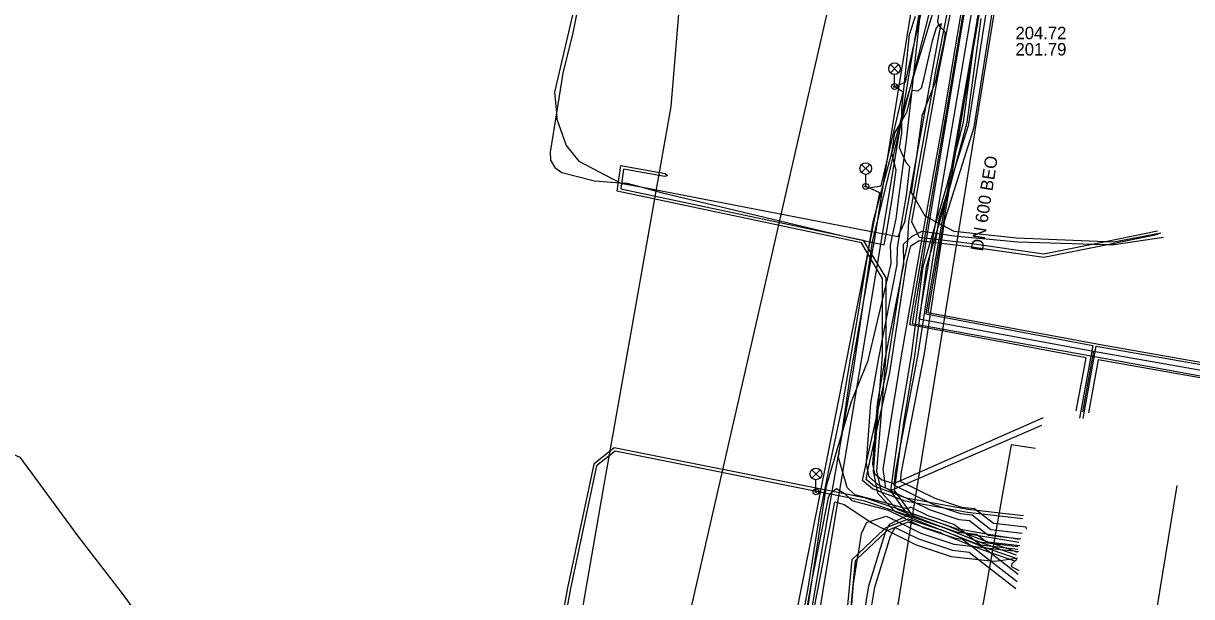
# Model space of a CAD drawing. Extents: x -596228 to -595156, y -1161235 to -1159373.
# Drawn here: x -595916.2 to -595841.1, y -1160088.8 to -1160051.9 of the extents above; entities that cross this region are included whole.
import ezdxf

# ---------------------------------------------------------------- set-up
doc = ezdxf.new("R2010")
doc.units = 0
for name, color, linetype in [('Vrstva 1', 7, 'Continuous'), ('Vrstva 12', 7, 'Continuous'), ('Vrstva 14', 7, 'Continuous'), ('Vrstva 25', 7, 'Continuous'), ('Vrstva 26', 7, 'Continuous'), ('Vrstva 33', 7, 'Continuous'), ('Vrstva 37', 7, 'Continuous'), ('Vrstva 4', 7, 'Continuous'), ('Vrstva 42', 7, 'Continuous'), ('Vrstva 44', 7, 'Continuous'), ('Vrstva 53', 7, 'Continuous'), ('Vrstva 55', 7, 'Continuous')]:
    doc.layers.add(name, color=color, linetype=linetype)

msp = doc.modelspace()

# ---------------------------------------------------------------- linework, layer by layer
at = {"layer": 'Vrstva 1'}
for p, q in [((-595878.63, -1160112.85), (-595863.23, -1160045.57)), ((-595853.63, -1160050.15), (-595860.88, -1160094.77))]:
    msp.add_line(p, q, dxfattribs=at)
at = {"layer": 'Vrstva 12'}
msp.add_lwpolyline([(-595873.83, -1160048.21), (-595874.58, -1160057.28), (-595878.97, -1160081.97), (-595886.34, -1160124.44), (-595887.99, -1160133.91), (-595889.12, -1160140.39), (-595891.94, -1160156.53), (-595892.78, -1160161.36), (-595893.73, -1160166.74)], dxfattribs=at)
at = {"layer": 'Vrstva 14'}
msp.add_lwpolyline([(-595903.525, -1160327.591), (-595903.438, -1160327.11), (-595895.992, -1160276.218), (-595895.362, -1160271.913), (-595894.416, -1160266.829), (-595893.077, -1160257.958), (-595892.847, -1160256.335), (-595887.94, -1160223.167), (-595881.65, -1160186.81), (-595876.814, -1160159.541), (-595869.649, -1160117.522), (-595863.209, -1160078.856), (-595858.091, -1160048.124), (-595857.576, -1160045.207), (-595855.994, -1160045.422), (-595855.543, -1160042.523), (-595857.05, -1160042.292), (-595850.5, -1160006.311), (-595840.026, -1160007.969)], dxfattribs=at)
at = {"layer": 'Vrstva 25'}
for points in [[(-595848.913, -1160014.604), (-595851.258, -1160027.646), (-595852.717, -1160036.135), (-595854.448, -1160046.34), (-595856.426, -1160058.005), (-595858.649, -1160070.917), (-595847.414, -1160073.01)], [(-595847.414, -1160073.01), (-595847.739, -1160074.765), (-595848.135, -1160076.908)], [(-595847.414, -1160073.01), (-595832.961, -1160075.546), (-595834.372, -1160084.741), (-595836.409, -1160097.343), (-595826.834, -1160101.575), (-595815.738, -1160106.435), (-595812.472, -1160107.597), (-595809.986, -1160108.26), (-595808.287, -1160108.633), (-595806.429, -1160108.923), (-595791.586, -1160111.411), (-595780.465, -1160113.2), (-595779.852, -1160109.66)]]:
    msp.add_lwpolyline(points, dxfattribs=at)
at = {"layer": 'Vrstva 26'}
for points in [[(-595848.334, -1160014.211), (-595850.766, -1160027.733), (-595852.224, -1160036.219), (-595853.955, -1160046.424), (-595855.933, -1160058.089), (-595858.073, -1160070.515), (-595847.323, -1160072.519)], [(-595847.898, -1160073.429), (-595859.226, -1160071.318), (-595856.918, -1160057.921), (-595854.941, -1160046.256), (-595853.21, -1160036.051), (-595851.751, -1160027.56), (-595849.492, -1160014.998)], [(-595847.328, -1160072.518), (-595832.393, -1160075.138), (-595833.878, -1160084.819), (-595835.854, -1160097.042), (-595826.633, -1160101.117), (-595815.554, -1160105.97), (-595812.323, -1160107.119), (-595809.868, -1160107.774), (-595808.195, -1160108.142), (-595806.349, -1160108.429), (-595791.505, -1160110.918), (-595780.873, -1160112.627), (-595780.345, -1160109.575)], [(-595848.528, -1160076.835), (-595848.132, -1160074.692), (-595847.898, -1160073.429)], [(-595847.111, -1160073.571), (-595847.345, -1160074.838), (-595847.741, -1160076.981)], [(-595779.429, -1160110.146), (-595780.056, -1160113.772), (-595791.667, -1160111.904), (-595806.509, -1160109.416), (-595808.38, -1160109.125), (-595810.104, -1160108.746), (-595812.62, -1160108.075), (-595815.923, -1160106.9), (-595827.035, -1160102.032), (-595836.965, -1160097.644), (-595834.866, -1160084.663), (-595833.53, -1160075.954), (-595847.111, -1160073.571)]]:
    msp.add_lwpolyline(points, dxfattribs=at)
at = {"layer": 'Vrstva 33'}
for p, q in [((-595860.475, -1160054.575), (-595859.945, -1160055.105)), ((-595860.475, -1160055.105), (-595859.945, -1160054.575)), ((-595860.21, -1160055.99), (-595860.21, -1160055.215)), ((-595862.325, -1160060.995), (-595861.795, -1160061.525)), ((-595862.325, -1160061.525), (-595861.795, -1160060.995)), ((-595862.06, -1160062.41), (-595862.06, -1160061.635)), ((-595865.525, -1160080.635), (-595864.995, -1160081.165)), ((-595865.525, -1160081.165), (-595864.995, -1160080.635)), ((-595865.26, -1160082.05), (-595865.26, -1160081.275))]:
    msp.add_line(p, q, dxfattribs=at)
for centre, radius in [((-595860.21, -1160054.84), 0.375), ((-595860.21, -1160055.99), 0.19), ((-595860.21, -1160055.99), 0.05), ((-595862.06, -1160061.26), 0.375), ((-595862.06, -1160062.41), 0.19), ((-595862.06, -1160062.41), 0.05), ((-595865.26, -1160080.9), 0.375), ((-595865.26, -1160082.05), 0.19), ((-595865.26, -1160082.05), 0.05)]:
    msp.add_circle(centre, radius, dxfattribs=at)
at = {"layer": 'Vrstva 37'}
for points in [[(-595851.153, -1160079.274), (-595852.714, -1160079.02), (-595862.455, -1160134.068), (-595836.577, -1160138.534)], [(-595842.059, -1160081.643), (-595848.753, -1160122.538), (-595834.439, -1160125.011), (-595836.577, -1160138.534)]]:
    msp.add_lwpolyline(points, dxfattribs=at)
at = {"layer": 'Vrstva 42'}
for points in [[(-595873.688, -1159960.969), (-595873.136, -1159957.91), (-595871.902, -1159958.088), (-595863.25, -1159959.53), (-595863.9, -1159965.29), (-595865.673, -1159976.949), (-595867.053, -1159989.854), (-595868.25, -1159989.709), (-595873.971, -1159989.019), (-595874.999, -1159988.861), (-595876.151, -1159992.513), (-595876.588, -1159993.79), (-595863.441, -1159998.192), (-595865.906, -1160011.02), (-595857.067, -1160012.572), (-595848.508, -1160014.294), (-595852.168, -1160035.065), (-595855.053, -1160052.565), (-595858.203, -1160070.6), (-595847.46, -1160072.642), (-595848.325, -1160077.311)], [(-595916.617, -1159981.581), (-595914.21, -1159982.379), (-595897.57, -1159987.853), (-595877.263, -1159994.535), (-595864.428, -1159998.802), (-595866.813, -1160011.736), (-595857.199, -1160013.352), (-595849.351, -1160014.93), (-595853.123, -1160036.433), (-595855.896, -1160052.235), (-595859.081, -1160071.227), (-595847.219, -1160073.379), (-595833.399, -1160075.892)], [(-595852.082, -1160085.098), (-595852.831, -1160085.013), (-595854.172, -1160084.86), (-595854.297, -1160084.763), (-595855.384, -1160083.917), (-595856.047, -1160083.842), (-595857.906, -1160083.223), (-595860.075, -1160082.16), (-595860.444, -1160081.979), (-595860.763, -1160081.822), (-595860.932, -1160080.592), (-595859.753, -1160073.316), (-595858.179, -1160064.287), (-595857.105, -1160058.32), (-595855.189, -1160046.9), (-595853.954, -1160042.986), (-595852.648, -1160041.748), (-595851.862, -1160041.003)], [(-595853.723, -1160047.284), (-595855.486, -1160058.519), (-595856.334, -1160061.214), (-595857.365, -1160064.492), (-595857.474, -1160065.204), (-595858.703, -1160073.211), (-595859.847, -1160079.116), (-595860.155, -1160080.704), (-595860.253, -1160081.627), (-595860.197, -1160081.654), (-595857.754, -1160082.852), (-595855.96, -1160083.449), (-595855.225, -1160083.533), (-595854.015, -1160084.476), (-595852.006, -1160084.704)], [(-595851.721, -1160084.459), (-595851.738, -1160084.333), (-595853.858, -1160084.091), (-595855.072, -1160083.147), (-595855.874, -1160083.057), (-595857.602, -1160082.481), (-595859.836, -1160081.386), (-595859.761, -1160080.774), (-595858.309, -1160073.279), (-595856.975, -1160064.582), (-595855.096, -1160058.611), (-595853.319, -1160047.289)], [(-595852.254, -1160087.365), (-595853.422, -1160086.457), (-595854.083, -1160085.943), (-595854.487, -1160085.629), (-595854.581, -1160085.556), (-595854.676, -1160085.482), (-595855.101, -1160085.152), (-595855.155, -1160085.11), (-595855.633, -1160084.738), (-595855.694, -1160084.69), (-595855.699, -1160084.687), (-595855.968, -1160084.478), (-595856.391, -1160084.149), (-595858.058, -1160083.594), (-595859.181, -1160083.043), (-595859.377, -1160083.136), (-595859.395, -1160083.144), (-595859.669, -1160083.071), (-595860.301, -1160082.903), (-595860.669, -1160082.805), (-595862.762, -1160082.247), (-595863.265, -1160081.765), (-595863.809, -1160079.844), (-595863.084, -1160074.815), (-595861.716, -1160067.103), (-595861.662, -1160066.801), (-595861.526, -1160066.033), (-595860.238, -1160057.936), (-595858.755, -1160048.787)], [(-595852.372, -1160086.12), (-595853.427, -1160085.75), (-595853.934, -1160085.572), (-595854.944, -1160085.217), (-595855.101, -1160085.152), (-595856.317, -1160084.65), (-595856.895, -1160084.411), (-595856.997, -1160084.369), (-595857.125, -1160084.316), (-595857.352, -1160084.24), (-595858.289, -1160083.926), (-595859.301, -1160083.587), (-595859.325, -1160083.554), (-595859.418, -1160083.422), (-595859.487, -1160083.326), (-595859.669, -1160083.071), (-595860.445, -1160081.986), (-595860.444, -1160081.979), (-595859.819, -1160077.445), (-595859.129, -1160073.285), (-595858.378, -1160067.559), (-595856.826, -1160062.303), (-595855.768, -1160058.271), (-595854.869, -1160051.583)], [(-595854.671, -1160051.617), (-595855.572, -1160058.309), (-595856.334, -1160061.214), (-595856.634, -1160062.357), (-595857.474, -1160065.204), (-595858.182, -1160067.601), (-595858.931, -1160073.315), (-595859.621, -1160077.475), (-595859.847, -1160079.116), (-595860.197, -1160081.654), (-595860.236, -1160081.934), (-595860.075, -1160082.16), (-595859.377, -1160083.136), (-595859.176, -1160083.418), (-595857.055, -1160084.129), (-595856.826, -1160084.223), (-595855.705, -1160084.686), (-595855.694, -1160084.69), (-595855.541, -1160084.754), (-595854.873, -1160085.03), (-595854.386, -1160085.201), (-595854.227, -1160085.257), (-595853.889, -1160085.375), (-595853.016, -1160085.682), (-595852.536, -1160085.851), (-595852.337, -1160085.921)], [(-595852.293, -1160085.769), (-595853.016, -1160085.682), (-595853.934, -1160085.572), (-595854.676, -1160085.482), (-595854.795, -1160085.468), (-595856.365, -1160084.846), (-595857.426, -1160084.426), (-595859.464, -1160083.619), (-595860.157, -1160083.345), (-595860.204, -1160083.295), (-595860.498, -1160082.985), (-595860.669, -1160082.805), (-595861.262, -1160082.178), (-595861.561, -1160080.736), (-595860.98, -1160073.256), (-595860.98, -1160068.338), (-595861.716, -1160067.103), (-595862.344, -1160066.049), (-595878.038, -1160062.714), (-595877.812, -1160061.058), (-595874.948, -1160061.572), (-595874.806, -1160061.699)], [(-595874.806, -1160061.699), (-595874.985, -1160061.765), (-595877.642, -1160061.292), (-595877.814, -1160062.556), (-595862.216, -1160065.871), (-595861.662, -1160066.801), (-595860.78, -1160068.282), (-595860.78, -1160073.264), (-595861.359, -1160080.724), (-595861.078, -1160082.082), (-595860.301, -1160082.903), (-595860.094, -1160083.121), (-595860.043, -1160083.175), (-595859.418, -1160083.422), (-595859.216, -1160083.502), (-595858.889, -1160083.632), (-595857.352, -1160084.24), (-595857.182, -1160084.307), (-595857.064, -1160084.354), (-595856.317, -1160084.65), (-595855.155, -1160085.11), (-595854.745, -1160085.272), (-595853.889, -1160085.375), (-595852.269, -1160085.571)], [(-595848.094, -1160077.345), (-595847.239, -1160072.677), (-595832.53, -1160075.26)], [(-595852.193, -1160085.121), (-595852.831, -1160085.013), (-595854.297, -1160084.763), (-595855.968, -1160084.478), (-595856.175, -1160084.443), (-595856.826, -1160084.223), (-595859.487, -1160083.326), (-595860.094, -1160083.121), (-595860.498, -1160082.985), (-595862.074, -1160082.453), (-595863.404, -1160082.186), (-595864.175, -1160082.032), (-595878.226, -1160079.213), (-595879.54, -1160080.264), (-595881.238, -1160088.221), (-595883.868, -1160102.562), (-595885.758, -1160112.701), (-595890.428, -1160136.561), (-595890.453, -1160136.9), (-595890.51, -1160137.05)], [(-595852.227, -1160085.319), (-595854.798, -1160084.88), (-595855.541, -1160084.754), (-595855.633, -1160084.738), (-595856.225, -1160084.637), (-595856.895, -1160084.411), (-595857.064, -1160084.354), (-595859.372, -1160083.576), (-595860.204, -1160083.295), (-595862.126, -1160082.647), (-595863.135, -1160082.444), (-595864.367, -1160082.197), (-595878.174, -1160079.427), (-595879.36, -1160080.376), (-595881.042, -1160088.259), (-595883.672, -1160102.598)], [(-595866.694, -1160094.345), (-595865.55, -1160087.923), (-595864.45, -1160082.424), (-595864.367, -1160082.197), (-595864.366, -1160082.193), (-595864.175, -1160082.032), (-595863.949, -1160081.842), (-595863.452, -1160082.14), (-595863.404, -1160082.186), (-595863.135, -1160082.444), (-595862.965, -1160082.607), (-595860.609, -1160083.235), (-595859.821, -1160083.619), (-595859.645, -1160083.705), (-595859.411, -1160083.821), (-595858.442, -1160084.297), (-595858.362, -1160084.336), (-595857.141, -1160084.742), (-595856.307, -1160085.02), (-595855.857, -1160085.071), (-595855.305, -1160085.501), (-595855.251, -1160085.543), (-595854.04, -1160086.484), (-595852.331, -1160087.813)], [(-595875.884, -1160147.461), (-595871.512, -1160122.724), (-595867.647, -1160100.73), (-595867.366, -1160099.13), (-595866.82, -1160096.978), (-595864.056, -1160082.698), (-595863.457, -1160082.87), (-595861.807, -1160083.949), (-595861.622, -1160084.07), (-595860.866, -1160084.442), (-595860.721, -1160084.513), (-595860.668, -1160084.539), (-595860.366, -1160084.688), (-595858.818, -1160085.449), (-595856.567, -1160086.199), (-595854.802, -1160086.398), (-595854.04, -1160086.484), (-595853.812, -1160086.51), (-595853.422, -1160086.457), (-595852.843, -1160086.379), (-595852.408, -1160086.32), (-595852.315, -1160086.307)], [(-595863.68, -1160094.364), (-595862.936, -1160086.393), (-595862.536, -1160086.016), (-595860.866, -1160084.442), (-595860.795, -1160084.374), (-595860.614, -1160084.302), (-595859.911, -1160084.021), (-595859.411, -1160083.821), (-595859.33, -1160083.788), (-595857.426, -1160084.426), (-595857.195, -1160084.504), (-595856.365, -1160084.846), (-595855.016, -1160085.403), (-595854.581, -1160085.556), (-595854.319, -1160085.648), (-595852.408, -1160086.32)], [(-595863.415, -1160094.933), (-595862.846, -1160087.963), (-595862.587, -1160086.339), (-595862.536, -1160086.016), (-595862.332, -1160084.738), (-595861.994, -1160084.009), (-595861.807, -1160083.949), (-595860.746, -1160083.611), (-595860.108, -1160083.924), (-595859.911, -1160084.021), (-595859.67, -1160084.14), (-595858.514, -1160084.707), (-595856.393, -1160085.413), (-595855.251, -1160085.543), (-595855.185, -1160085.55), (-595854.487, -1160085.629), (-595854.319, -1160085.648), (-595853.427, -1160085.75), (-595852.536, -1160085.851), (-595852.234, -1160085.885)], [(-595862.944, -1160094.674), (-595861.858, -1160088.086), (-595860.816, -1160084.7), (-595860.786, -1160084.641), (-595860.721, -1160084.513), (-595860.614, -1160084.302), (-595860.522, -1160084.12), (-595860.108, -1160083.924), (-595859.645, -1160083.705), (-595859.464, -1160083.619), (-595859.372, -1160083.576), (-595859.325, -1160083.554), (-595859.216, -1160083.502), (-595859.184, -1160083.487), (-595858.889, -1160083.632), (-595858.289, -1160083.926), (-595858.21, -1160083.965), (-595857.182, -1160084.307), (-595856.997, -1160084.369), (-595856.22, -1160084.628), (-595855.705, -1160084.686), (-595855.699, -1160084.687), (-595854.936, -1160084.773), (-595854.798, -1160084.88), (-595854.386, -1160085.201), (-595854.329, -1160085.245), (-595854.227, -1160085.257), (-595852.158, -1160085.492)], [(-595869.636, -1160134.237), (-595869.522, -1160132.94), (-595866.263, -1160116.198), (-595864.385, -1160102.93), (-595862.632, -1160095.129), (-595861.47, -1160088.182), (-595860.478, -1160084.891), (-595860.366, -1160084.688), (-595860.177, -1160084.342), (-595860.174, -1160084.337), (-595860.169, -1160084.339), (-595858.666, -1160085.078), (-595856.48, -1160085.806), (-595855.408, -1160085.927), (-595854.802, -1160086.398), (-595852.407, -1160088.26)], [(-595852.443, -1160086.519), (-595852.467, -1160086.511), (-595852.843, -1160086.379), (-595854.083, -1160085.943), (-595855.087, -1160085.59), (-595855.185, -1160085.55), (-595855.305, -1160085.501), (-595857.141, -1160084.742), (-595857.265, -1160084.691), (-595858.442, -1160084.297), (-595859.324, -1160084.001), (-595859.67, -1160084.14), (-595860.169, -1160084.339), (-595860.177, -1160084.342), (-595860.668, -1160084.539), (-595860.685, -1160084.546), (-595860.786, -1160084.641), (-595862.587, -1160086.339), (-595862.744, -1160086.487), (-595863.48, -1160094.376)], [(-595852.338, -1160086.428), (-595852.364, -1160086.427), (-595852.467, -1160086.511), (-595852.674, -1160086.68), (-595852.684, -1160086.852), (-595852.209, -1160087.1)]]:
    msp.add_lwpolyline(points, dxfattribs=at)
at = {"layer": 'Vrstva 44'}
for points in [[(-595858.401, -1160057.773), (-595858.18, -1160057.213), (-595857.755, -1160056.136), (-595857.586, -1160055.707), (-595857.029, -1160053.114), (-595856.931, -1160052.504), (-595857.035, -1160052.395), (-595857.245, -1160052.174), (-595857.364, -1160052.049), (-595857.365, -1160052.048), (-595857.43, -1160051.816), (-595856.979, -1160048.701), (-595856.277, -1160043.862), (-595855.165, -1160035.357), (-595852.649, -1160021.312), (-595852.169, -1160020.85), (-595851.405, -1160020.397), (-595850.525, -1160020.192), (-595850.443, -1160020.173), (-595849.791, -1160020.273), (-595842.55, -1160020.946), (-595841.682, -1160021.027)], [(-595843.312, -1160065.292), (-595846.656, -1160065.967), (-595847.396, -1160066.117), (-595850.608, -1160066.765), (-595855.392, -1160066.081), (-595858.609, -1160065.695), (-595858.732, -1160065.442), (-595859.097, -1160064.695), (-595858.842, -1160063.28), (-595857.375, -1160055.152), (-595855.334, -1160044.772), (-595854.342, -1160043.176), (-595851.692, -1160041.584), (-595848.26, -1160039.792), (-595846.43, -1160038.018), (-595844.919, -1160035.362), (-595841.777, -1160023.635), (-595841.41, -1160022.76), (-595841.279, -1160022.199)], [(-595867.55, -1160097.7), (-595865.77, -1160088.25), (-595865.01, -1160083.51), (-595864.31, -1160080.03), (-595863.56, -1160076.52), (-595862.55, -1160070.62), (-595861.798, -1160065.97), (-595861.691, -1160065.304), (-595861.59, -1160064.68), (-595860.375, -1160060.257), (-595859.871, -1160058.422), (-595859.737, -1160057.936), (-595859.45, -1160056.89), (-595858.987, -1160055.362), (-595857.7, -1160051.11), (-595856.979, -1160048.701), (-595856.28, -1160046.37), (-595856.052, -1160045.776), (-595856.003, -1160045.65), (-595855.58, -1160044.55)], [(-595851.957, -1160083.784), (-595855.525, -1160083.38), (-595859.516, -1160082.655), (-595861.622, -1160081.854), (-595862.265, -1160081.324), (-595862.004, -1160080.146), (-595861.411, -1160077.463), (-595860.717, -1160074.329), (-595859.695, -1160067.759), (-595859.643, -1160067.421), (-595859.609, -1160067.204), (-595859.367, -1160066.203), (-595859.351, -1160065.86), (-595859.297, -1160064.673), (-595858.996, -1160063.008), (-595857.755, -1160056.136), (-595857.571, -1160055.116), (-595857.035, -1160052.395), (-595855.524, -1160044.718)], [(-595877.641, -1160157.25), (-595877.206, -1160154.877), (-595875.823, -1160146.872), (-595874.194, -1160137.323), (-595870.493, -1160116.878), (-595869.152, -1160108.721), (-595866.815, -1160096.285), (-595864.579, -1160081.663), (-595862.969, -1160076.234), (-595861.913, -1160073.61), (-595860.434, -1160067.371), (-595860.472, -1160066.199), (-595860.336, -1160065.565), (-595860.108, -1160064.5), (-595859.919, -1160062.97), (-595859.588, -1160060.589), (-595859.432, -1160059.468), (-595859.081, -1160056.226), (-595858.987, -1160055.362), (-595857.892, -1160045.25)], [(-595879.809, -1160047.133), (-595880.898, -1160052.528), (-595881.528, -1160055.128), (-595881.945, -1160057.687), (-595882.356, -1160060.216), (-595882.335, -1160060.719), (-595882.049, -1160061.198), (-595881.59, -1160061.525), (-595879.507, -1160062.058), (-595877.852, -1160062.177), (-595877.411, -1160062.209), (-595876.523, -1160062.443), (-595875.203, -1160062.792), (-595863.274, -1160065.66), (-595861.798, -1160065.97), (-595860.873, -1160066.164), (-595860.743, -1160065.487), (-595860.654, -1160065.023), (-595860.334, -1160063.049), (-595860.105, -1160061.368), (-595860.381, -1160060.298), (-595860.375, -1160060.257), (-595860.182, -1160058.96), (-595859.871, -1160058.422), (-595859.74, -1160058.196), (-595859.397, -1160057.603), (-595859.087, -1160056.226), (-595859.081, -1160056.226), (-595858.687, -1160056.258), (-595858.468, -1160056.07), (-595858.335, -1160055.515), (-595857.757, -1160052.954), (-595857.518, -1160052.223), (-595857.366, -1160052.051), (-595857.364, -1160052.049), (-595857.198, -1160051.924)], [(-595880.79, -1160050.84), (-595882.06, -1160056.34), (-595881.945, -1160057.687), (-595881.91, -1160058.09), (-595881.31, -1160059.79), (-595880.5, -1160060.78), (-595877.852, -1160062.177), (-595877.822, -1160062.193), (-595876.523, -1160062.443), (-595861.691, -1160065.304), (-595860.743, -1160065.487), (-595860.336, -1160065.565), (-595859.975, -1160065.635), (-595859.843, -1160065.335), (-595859.557, -1160064.683), (-595858.781, -1160060.474), (-595858.18, -1160057.213), (-595857.807, -1160055.189), (-595857.245, -1160052.174), (-595857.198, -1160051.924)], [(-595850.755, -1160077.783), (-595860.427, -1160081.962), (-595861.255, -1160081.611), (-595861.837, -1160081.08), (-595861.919, -1160080.685), (-595862.011, -1160080.237), (-595862.004, -1160080.146), (-595861.728, -1160076.348), (-595861.216, -1160073.429), (-595860.038, -1160067.429), (-595860.015, -1160066.347), (-595859.843, -1160065.335), (-595859.448, -1160063.003), (-595859.236, -1160061.16), (-595859.433, -1160060.922), (-595859.588, -1160060.589), (-595859.894, -1160059.929), (-595859.748, -1160058.989), (-595859.74, -1160058.196), (-595859.737, -1160057.936), (-595859.732, -1160057.422), (-595859.242, -1160052.634), (-595858.859, -1160051.464)], [(-595843.087, -1160065.422), (-595846.11, -1160065.989), (-595846.656, -1160065.967), (-595852.362, -1160065.739), (-595856.386, -1160065.319), (-595858.242, -1160064.333), (-595858.842, -1160063.28), (-595858.996, -1160063.008), (-595859.109, -1160062.81), (-595858.781, -1160060.474), (-595858.402, -1160057.773)], [(-595851.922, -1160083.587), (-595855.495, -1160083.182), (-595859.462, -1160082.461), (-595861.52, -1160081.678), (-595862.043, -1160081.248), (-595861.919, -1160080.685), (-595861.515, -1160078.861), (-595860.521, -1160074.367), (-595859.413, -1160067.242), (-595859.169, -1160066.231), (-595858.633, -1160065.893), (-595855.418, -1160066.279), (-595850.602, -1160066.967), (-595846.516, -1160066.143), (-595843.272, -1160065.488)], [(-595859.66, -1160066.141), (-595859.351, -1160065.86), (-595859.07, -1160065.603), (-595858.732, -1160065.442), (-595858.432, -1160065.299), (-595856.386, -1160065.582), (-595852.285, -1160065.972)], [(-595852.285, -1160065.972), (-595847.396, -1160066.117), (-595846.516, -1160066.143), (-595846.093, -1160066.155), (-595842.919, -1160065.68)], [(-595859.66, -1160066.141), (-595859.643, -1160067.421), (-595859.642, -1160067.487), (-595859.695, -1160067.759), (-595860.823, -1160073.502), (-595861.331, -1160076.397), (-595861.411, -1160077.463), (-595861.515, -1160078.861), (-595861.62, -1160080.266), (-595861.488, -1160080.867), (-595861.036, -1160081.269), (-595860.265, -1160081.511), (-595850.626, -1160077.269)]]:
    msp.add_lwpolyline(points, dxfattribs=at)
at = {"layer": 'Vrstva 53'}
msp.add_lwpolyline([(-595834.49, -1160024.39), (-595844.31, -1160035.25), (-595847.42, -1160039.55), (-595847.57, -1160039.84), (-595848.73, -1160040.53), (-595850.81, -1160041.8), (-595852.8, -1160043.6), (-595853.34, -1160044.28), (-595853.98, -1160044.54), (-595855.28, -1160044.61), (-595856.08, -1160045.82), (-595856.8, -1160047.16), (-595857.54, -1160049.46), (-595859.63, -1160057.71), (-595861.65, -1160065.98), (-595862.86, -1160074.22), (-595864.25, -1160082.03), (-595866.66, -1160096.08), (-595868.31, -1160105.61), (-595869.84, -1160114.54), (-595871.58, -1160124.29), (-595873.02, -1160132.72), (-595874.46, -1160140.81), (-595876.52, -1160152.45)], dxfattribs=at)
at = {"layer": 'Vrstva 55'}
for points in [[(-595862.06, -1160062.41), (-595861.87, -1160062.51), (-595861.08, -1160062.38), (-595859.65, -1160056.34), (-595860.21, -1160055.99), (-595859.5, -1160055.71), (-595858.4, -1160050.79), (-595857.59, -1160047.91), (-595856.92, -1160045.78), (-595855.89, -1160044.36), (-595854.2, -1160042.79), (-595852.47, -1160041.12), (-595852.44, -1160040.81), (-595851.88, -1160040.53), (-595849.94, -1160039.27), (-595847.27, -1160038.08), (-595845.36, -1160037.68), (-595845.13, -1160037.27), (-595845.81, -1160037.66), (-595846.2, -1160037.41), (-595841.92, -1160023.82), (-595839.99, -1160023.02)], [(-595953.14, -1160066.86), (-595953.59, -1160065.3), (-595952.99, -1160064.31), (-595945.28, -1160059.37), (-595942.81, -1160058.82), (-595940.24, -1160059.39), (-595938.78, -1160060.75), (-595927.72, -1160074.78), (-595916.43, -1160079.83), (-595912.7, -1160084.91), (-595909.8, -1160088.68), (-595905.31, -1160094.89), (-595905.19, -1160094.98)], [(-595901.722, -1160303.649), (-595901.92, -1160299.12), (-595902.19, -1160291.297), (-595890.66, -1160226.32), (-595886.19, -1160198.97), (-595881.04, -1160171.41), (-595876.29, -1160143.99), (-595871.58, -1160116.92), (-595868.39, -1160099.39), (-595861.162, -1160062.826), (-595862.06, -1160062.41)]]:
    msp.add_lwpolyline(points, dxfattribs=at)

# ---------------------------------------------------------------- texts
at = {"layer": 'Vrstva 4'}
for s, p in [('204.72', (-595852.434, -1160052.943)), ('201.79', (-595852.434, -1160053.993))]:
    msp.add_text(s, height=0.8, dxfattribs=at).set_placement(p)
msp.add_text('DN 600 BEO', height=0.8, rotation=81, dxfattribs=at).set_placement((-595854.533, -1160066.618))

doc.saveas('drawing.dxf')
